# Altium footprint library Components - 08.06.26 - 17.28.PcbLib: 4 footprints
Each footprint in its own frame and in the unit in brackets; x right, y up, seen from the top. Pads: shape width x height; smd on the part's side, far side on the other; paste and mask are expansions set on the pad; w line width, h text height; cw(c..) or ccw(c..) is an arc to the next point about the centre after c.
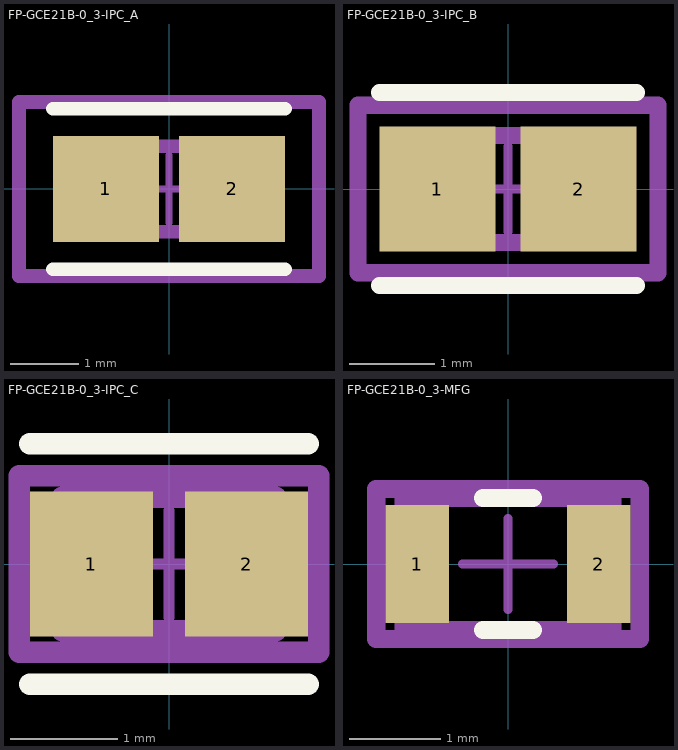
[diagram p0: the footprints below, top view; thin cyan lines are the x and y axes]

## FP-GCE21B-0_3-IPC_A [mm]
pads (2):
  rect 1.553x1.556 smd paste+0 mask+0: 1(-0.925,0) 2(0.925,0)
Top Overlay:
  lines w0.2: -1.702,-1.178 1.702,-1.178 ; -1.702,1.178 1.702,1.178
Top Assembly:
  lines w0.2: -2.202,-1.278 2.202,-1.278 2.202,1.278 -2.202,1.278 -2.202,-1.278
  text ".Designator" at 0,0.188 h1
Top 3D Body:
  lines w0.2: -1,-0.625 1,-0.625 1,0.625 -1,0.625 -1,-0.625
Top Courtyard:
  lines w0.2: -2.202,-1.278 2.202,-1.278 2.202,1.278 -2.202,1.278 -2.202,-1.278
Top Component Center:
  lines w0.1: -0.5,0 0.5,0 ; 0,-0.5 0,0.5
3D body "Cap_Murata_GCE21BR71H104KA01L_eec.STEP": height 0.25, standoff 0, extent -2.202,-1.278 2.202,1.278

## FP-GCE21B-0_3-IPC_B [mm]
pads (2):
  rect 1.353x1.456 smd paste+0 mask+0: 1(-0.825,0) 2(0.825,0)
Top Overlay:
  lines w0.2: -1.502,-1.128 1.502,-1.128 ; -1.502,1.128 1.502,1.128
Top Assembly:
  lines w0.2: -1.752,-0.978 1.752,-0.978 1.752,0.978 -1.752,0.978 -1.752,-0.978
  text ".Designator" at 0,0.188 h1
Top 3D Body:
  lines w0.2: -1,-0.625 1,-0.625 1,0.625 -1,0.625 -1,-0.625
Top Courtyard:
  lines w0.2: -1.752,-0.978 1.752,-0.978 1.752,0.978 -1.752,0.978 -1.752,-0.978
Top Component Center:
  lines w0.1: -0.5,0 0.5,0 ; 0,-0.5 0,0.5
3D body "Cap_Murata_GCE21BR71H104KA01L_eec.STEP": height 0.25, standoff 0, extent -1.752,-0.978 1.752,0.978

## FP-GCE21B-0_3-IPC_C [mm]
pads (2):
  rect 1.153x1.356 smd paste+0 mask+0: 1(-0.725,0) 2(0.725,0)
Top Overlay:
  lines w0.2: -1.302,-1.125 1.302,-1.125 ; -1.302,1.125 1.302,1.125
Top Assembly:
  lines w0.2: -1.402,-0.825 1.402,-0.825 1.402,0.825 -1.402,0.825 -1.402,-0.825
  text ".Designator" at 0,0.188 h1
Top 3D Body:
  lines w0.2: -1,-0.625 1,-0.625 1,0.625 -1,0.625 -1,-0.625
Top Courtyard:
  lines w0.2: -1.402,-0.825 1.402,-0.825 1.402,0.825 -1.402,0.825 -1.402,-0.825
Top Component Center:
  lines w0.1: -0.5,0 0.5,0 ; 0,-0.5 0,0.5
3D body "Cap_Murata_GCE21BR71H104KA01L_eec.STEP": height 0.25, standoff 0, extent -1.402,-0.825 1.402,0.825

## FP-GCE21B-0_3-MFG [mm]
pads (2):
  rect 0.7x1.3 smd paste+0 mask+0: 1(-1,0) 2(1,0)
Top Overlay:
  lines w0.2: -0.275,-0.725 0.275,-0.725 ; -0.275,0.725 0.275,0.725
Top Assembly:
  lines w0.2: -1.45,-0.825 1.45,-0.825 1.45,0.825 -1.45,0.825 -1.45,-0.825
  text ".Designator" at 0,0.188 h1
Top 3D Body:
  lines w0.2: -1.15,-0.725 1.15,-0.725 1.15,0.725 -1.15,0.725 -1.15,-0.725
Top Courtyard:
  lines w0.2: -1.45,-0.825 1.45,-0.825 1.45,0.825 -1.45,0.825 -1.45,-0.825
Top Component Center:
  lines w0.1: -0.5,0 0.5,0 ; 0,-0.5 0,0.5
3D body "Cap_Murata_GCE21BR71H104KA01L_eec.STEP": height 0.25, standoff 0, extent -1.45,-0.825 1.45,0.825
